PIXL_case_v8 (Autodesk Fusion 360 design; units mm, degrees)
part number: 0.96Oled_W_4_Buttons
base_feature "Base Feature"
work_plane "WorkPlane1" AlongDistance -6.5 ExtraOffset 0
sketch "Sketch1" plane through (0, 0, -6.5) normal (0, 0, 1) x axis (1, 0, 0)
  line L1 (24.2, -27.5) -> (-24.2, -27.5)
  line L2 (24.2, 15.7) -> (24.2, -27.5)
  line L3 (-24.2, 15.7) -> (24.2, 15.7)
  line L4 (-24.2, -27.5) -> (-24.2, 15.7)
extrude "Extrude1" new body sketch "Sketch1" along normal blind 11.8
fillet "Fillet1" radius 5
fillet "Fillet2" radius 1.4
work_plane "WorkPlane2" AlongDistance -6.5 ExtraOffset 0
sketch "Sketch2" plane through (0, 0, -6.5) normal (0, 0, 1) x axis (1, 0, 0)
  line L1 (22.2, -25.5) -> (-22.2, -25.5)
  line L2 (22.2, 13.7) -> (22.2, -25.5)
  line L3 (-22.2, 13.7) -> (22.2, 13.7)
  line L4 (-22.2, -25.5) -> (-22.2, 13.7)
extrude "Extrude2" cut sketch "Sketch2" along normal blind 9.3
fillet "Fillet3" radius 1.7
work_plane "WorkPlane3" AlongDistance 2.79 ExtraOffset 0
sketch "Sketch3" plane through (0, 0, 2.79) normal (0, 0, 1) x axis (1, 0, 0)
  line L1 (20.7, -11.3) -> (11, -11.3)
  line L2 (20.7, 11.7) -> (20.7, -11.3)
  line L3 (11, 11.7) -> (20.7, 11.7)
  line L4 (11, -11.3) -> (11, 11.7)
extrude "Extrude3" cut sketch "Sketch3" along normal blind 1.56
work_plane "WorkPlane4" AlongDistance 2.79 ExtraOffset 0
sketch "Sketch4" plane through (0, 0, 2.79) normal (0, 0, 1) x axis (1, 0, 0)
  line L1 (10, 9.6) -> (-10.8, 9.6)
  line L2 (10, 12.2) -> (10, 9.6)
  line L3 (-10.8, 12.2) -> (10, 12.2)
  line L4 (-10.8, 9.6) -> (-10.8, 12.2)
extrude "Extrude4" cut sketch "Sketch4" along normal blind 0.91
work_plane "WorkPlane5" AlongDistance 4.34 ExtraOffset 0
sketch "Sketch5" plane through (0, 0, 4.34) normal (0, 0, 1) x axis (1, 0, 0)
  line L1 (12.1, 5.6) -> (11.5, 5.6)
  line L2 (12.1, 11.8) -> (12.1, 5.6)
  line L3 (11.5, 11.8) -> (12.1, 11.8)
  line L4 (11.5, 5.6) -> (11.5, 11.8)
extrude "Extrude5" cut sketch "Sketch5" along normal blind 1.06
work_plane "WorkPlane6" AlongDistance 4.34 ExtraOffset 0
sketch "Sketch6" plane through (0, 0, 4.34) normal (0, 0, 1) x axis (1, 0, 0)
  line L1 (19.6, 11.2) -> (11.5, 11.2)
  line L2 (19.6, 11.8) -> (19.6, 11.2)
  line L3 (11.5, 11.8) -> (19.6, 11.8)
  line L4 (11.5, 11.2) -> (11.5, 11.8)
extrude "Extrude6" cut sketch "Sketch6" along normal blind 1.06
work_plane "WorkPlane7" AlongDistance 4.34 ExtraOffset 0
sketch "Sketch7" plane through (0, 0, 4.34) normal (0, 0, 1) x axis (1, 0, 0)
  line L1 (19.6, 5.6) -> (11.5, 5.6)
  line L2 (19.6, 6.2) -> (19.6, 5.6)
  line L3 (11.5, 6.2) -> (19.6, 6.2)
  line L4 (11.5, 5.6) -> (11.5, 6.2)
extrude "Extrude7" cut sketch "Sketch7" along normal blind 1.06
work_plane "WorkPlane8" AlongDistance 4.34 ExtraOffset 0
sketch "Sketch8" plane through (0, 0, 4.34) normal (0, 0, 1) x axis (1, 0, 0)
  line L1 (12.1, -0.07) -> (11.5, -0.07)
  line L2 (12.1, 6.13) -> (12.1, -0.07)
  line L3 (11.5, 6.13) -> (12.1, 6.13)
  line L4 (11.5, -0.07) -> (11.5, 6.13)
extrude "Extrude8" cut sketch "Sketch8" along normal blind 1.06
work_plane "WorkPlane9" AlongDistance 4.34 ExtraOffset 0
sketch "Sketch9" plane through (0, 0, 4.34) normal (0, 0, 1) x axis (1, 0, 0)
  line L1 (19.6, 5.53) -> (11.5, 5.53)
  line L2 (19.6, 6.13) -> (19.6, 5.53)
  line L3 (11.5, 6.13) -> (19.6, 6.13)
  line L4 (11.5, 5.53) -> (11.5, 6.13)
extrude "Extrude9" cut sketch "Sketch9" along normal blind 1.06
work_plane "WorkPlane10" AlongDistance 4.34 ExtraOffset 0
sketch "Sketch10" plane through (0, 0, 4.34) normal (0, 0, 1) x axis (1, 0, 0)
  line L1 (19.6, -0.07) -> (11.5, -0.07)
  line L2 (19.6, 0.53) -> (19.6, -0.07)
  line L3 (11.5, 0.53) -> (19.6, 0.53)
  line L4 (11.5, -0.07) -> (11.5, 0.53)
extrude "Extrude10" cut sketch "Sketch10" along normal blind 1.06
work_plane "WorkPlane11" AlongDistance 4.34 ExtraOffset 0
sketch "Sketch11" plane through (0, 0, 4.34) normal (0, 0, 1) x axis (1, 0, 0)
  line L1 (12.1, -5.73) -> (11.5, -5.73)
  line L2 (12.1, 0.47) -> (12.1, -5.73)
  line L3 (11.5, 0.47) -> (12.1, 0.47)
  line L4 (11.5, -5.73) -> (11.5, 0.47)
extrude "Extrude11" cut sketch "Sketch11" along normal blind 1.06
work_plane "WorkPlane12" AlongDistance 4.34 ExtraOffset 0
sketch "Sketch12" plane through (0, 0, 4.34) normal (0, 0, 1) x axis (1, 0, 0)
  line L1 (19.6, -0.13) -> (11.5, -0.13)
  line L2 (19.6, 0.47) -> (19.6, -0.13)
  line L3 (11.5, 0.47) -> (19.6, 0.47)
  line L4 (11.5, -0.13) -> (11.5, 0.47)
extrude "Extrude12" cut sketch "Sketch12" along normal blind 1.06
work_plane "WorkPlane13" AlongDistance 4.34 ExtraOffset 0
sketch "Sketch13" plane through (0, 0, 4.34) normal (0, 0, 1) x axis (1, 0, 0)
  line L1 (19.6, -5.73) -> (11.5, -5.73)
  line L2 (19.6, -5.13) -> (19.6, -5.73)
  line L3 (11.5, -5.13) -> (19.6, -5.13)
  line L4 (11.5, -5.73) -> (11.5, -5.13)
extrude "Extrude13" cut sketch "Sketch13" along normal blind 1.06
work_plane "WorkPlane14" AlongDistance 4.34 ExtraOffset 0
sketch "Sketch14" plane through (0, 0, 4.34) normal (0, 0, 1) x axis (1, 0, 0)
  line L1 (12.1, -11.4) -> (11.5, -11.4)
  line L2 (12.1, -5.2) -> (12.1, -11.4)
  line L3 (11.5, -5.2) -> (12.1, -5.2)
  line L4 (11.5, -11.4) -> (11.5, -5.2)
extrude "Extrude14" cut sketch "Sketch14" along normal blind 1.06
work_plane "WorkPlane15" AlongDistance 4.34 ExtraOffset 0
sketch "Sketch15" plane through (0, 0, 4.34) normal (0, 0, 1) x axis (1, 0, 0)
  line L1 (19.6, -5.8) -> (11.5, -5.8)
  line L2 (19.6, -5.2) -> (19.6, -5.8)
  line L3 (11.5, -5.2) -> (19.6, -5.2)
  line L4 (11.5, -5.8) -> (11.5, -5.2)
extrude "Extrude15" cut sketch "Sketch15" along normal blind 1.06
work_plane "WorkPlane16" AlongDistance 4.34 ExtraOffset 0
sketch "Sketch16" plane through (0, 0, 4.34) normal (0, 0, 1) x axis (1, 0, 0)
  line L1 (19.6, -11.4) -> (11.5, -11.4)
  line L2 (19.6, -10.8) -> (19.6, -11.4)
  line L3 (11.5, -10.8) -> (19.6, -10.8)
  line L4 (11.5, -11.4) -> (11.5, -10.8)
extrude "Extrude16" cut sketch "Sketch16" along normal blind 1.06
work_plane "WorkPlane17" AlongDistance 4.34 ExtraOffset 0
sketch "Sketch17" plane through (0, 0, 4.34) normal (0, 0, 1) x axis (1, 0, 0)
  line L1 (20.7, 6.2) -> (18.4, 6.2)
  line L2 (20.7, 11.2) -> (20.7, 6.2)
  line L3 (18.4, 11.2) -> (20.7, 11.2)
  line L4 (18.4, 6.2) -> (18.4, 11.2)
extrude "Extrude17" cut sketch "Sketch17" along normal blind 0.46
work_plane "WorkPlane18" AlongDistance 4.34 ExtraOffset 0
sketch "Sketch18" plane through (0, 0, 4.34) normal (0, 0, 1) x axis (1, 0, 0)
  line L1 (20.7, 0.53) -> (18.4, 0.53)
  line L2 (20.7, 5.53) -> (20.7, 0.53)
  line L3 (18.4, 5.53) -> (20.7, 5.53)
  line L4 (18.4, 0.53) -> (18.4, 5.53)
extrude "Extrude18" cut sketch "Sketch18" along normal blind 0.46
work_plane "WorkPlane19" AlongDistance 4.34 ExtraOffset 0
sketch "Sketch19" plane through (0, 0, 4.34) normal (0, 0, 1) x axis (1, 0, 0)
  line L1 (20.7, -5.13) -> (18.4, -5.13)
  line L2 (20.7, -0.13) -> (20.7, -5.13)
  line L3 (18.4, -0.13) -> (20.7, -0.13)
  line L4 (18.4, -5.13) -> (18.4, -0.13)
extrude "Extrude19" cut sketch "Sketch19" along normal blind 0.46
work_plane "WorkPlane20" AlongDistance 4.34 ExtraOffset 0
sketch "Sketch20" plane through (0, 0, 4.34) normal (0, 0, 1) x axis (1, 0, 0)
  line L1 (20.7, -10.8) -> (18.4, -10.8)
  line L2 (20.7, -5.8) -> (20.7, -10.8)
  line L3 (18.4, -5.8) -> (20.7, -5.8)
  line L4 (18.4, -10.8) -> (18.4, -5.8)
extrude "Extrude20" cut sketch "Sketch20" along normal blind 0.46
work_plane "WorkPlane21" AlongDistance 2.79 ExtraOffset 0
sketch "Sketch21" plane through (0, 0, 2.79) normal (0, 0, 1) x axis (1, 0, 0)
  line L1 (7, -6.6) -> (-16.3, -6.6)
  line L2 (7, 6.4) -> (7, -6.6)
  line L3 (-16.3, 6.4) -> (7, 6.4)
  line L4 (-16.3, -6.6) -> (-16.3, 6.4)
extrude "Extrude21" cut sketch "Sketch21" along normal blind 2.61
chamfer "Chamfer1" distance 1.2
work_plane "WorkPlane22" AlongDistance 1.6 ExtraOffset 0
sketch "Sketch22" plane through (0, 0, 1.6) normal (0, 0, 1) x axis (1, 0, 0)
  circle C1 centre (-20.5, -12) radius 1.5
extrude "Extrude22" add sketch "Sketch22" along normal blind 1.21
work_plane "WorkPlane23" AlongDistance 0.3 ExtraOffset 0
sketch "Sketch23" plane through (0, 0, 0.3) normal (0, 0, 1) x axis (1, 0, 0)
  circle C1 centre (-20.5, -12) radius 0.88
extrude "Extrude23" add sketch "Sketch23" along normal blind 1.31
work_plane "WorkPlane24" AlongDistance 1.6 ExtraOffset 0
sketch "Sketch24" plane through (0, 0, 1.6) normal (0, 0, 1) x axis (1, 0, 0)
  circle C1 centre (-20.5, 12) radius 1.5
extrude "Extrude24" add sketch "Sketch24" along normal blind 1.21
work_plane "WorkPlane25" AlongDistance 0.3 ExtraOffset 0
sketch "Sketch25" plane through (0, 0, 0.3) normal (0, 0, 1) x axis (1, 0, 0)
  circle C1 centre (-20.5, 12) radius 0.88
extrude "Extrude25" add sketch "Sketch25" along normal blind 1.31
work_plane "WorkPlane26" AlongDistance 1.6 ExtraOffset 0
sketch "Sketch26" plane through (0, 0, 1.6) normal (0, 0, 1) x axis (1, 0, 0)
  circle C1 centre (20.5, -12) radius 1.5
extrude "Extrude26" add sketch "Sketch26" along normal blind 1.21
work_plane "WorkPlane27" AlongDistance 0.3 ExtraOffset 0
sketch "Sketch27" plane through (0, 0, 0.3) normal (0, 0, 1) x axis (1, 0, 0)
  circle C1 centre (20.5, -12) radius 0.88
extrude "Extrude27" add sketch "Sketch27" along normal blind 1.31
work_plane "WorkPlane28" AlongDistance 1.6 ExtraOffset 0
sketch "Sketch28" plane through (0, 0, 1.6) normal (0, 0, 1) x axis (1, 0, 0)
  circle C1 centre (20.5, 12) radius 1.5
extrude "Extrude28" add sketch "Sketch28" along normal blind 1.21
work_plane "WorkPlane29" AlongDistance 0.3 ExtraOffset 0
sketch "Sketch29" plane through (0, 0, 0.3) normal (0, 0, 1) x axis (1, 0, 0)
  circle C1 centre (20.5, 12) radius 0.88
extrude "Extrude29" add sketch "Sketch29" along normal blind 1.31
work_plane "WorkPlane30" AlongDistance 5.3 ExtraOffset 0
sketch "Sketch30" plane through (0, 0, 5.3) normal (0, 0, 1) x axis (1, 0, 0)
  line L1 (-16.5, -17.8) -> (-19.8, -17.8)
  line L2 (-16.5, -16.7) -> (-16.5, -17.8)
  line L3 (-19.8, -16.7) -> (-16.5, -16.7)
  line L4 (-19.8, -17.8) -> (-19.8, -16.7)
  line L5 (-18.7, -18.9) -> (-19.8, -18.9)
  line L6 (-18.7, -17.8) -> (-18.7, -18.9)
  line L7 (-19.8, -17.8) -> (-18.7, -17.8)
  line L8 (-19.8, -18.9) -> (-19.8, -17.8)
  line L9 (-15.4, -18.9) -> (-16.5, -18.9)
  line L10 (-15.4, -17.8) -> (-15.4, -18.9)
  line L11 (-16.5, -17.8) -> (-15.4, -17.8)
  line L12 (-16.5, -18.9) -> (-16.5, -17.8)
  line L13 (-18.7, -20) -> (-19.8, -20)
  line L14 (-18.7, -18.9) -> (-18.7, -20)
  line L15 (-19.8, -18.9) -> (-18.7, -18.9)
  line L16 (-19.8, -20) -> (-19.8, -18.9)
  line L17 (-15.4, -20) -> (-16.5, -20)
  line L18 (-15.4, -18.9) -> (-15.4, -20)
  line L19 (-16.5, -18.9) -> (-15.4, -18.9)
  line L20 (-16.5, -20) -> (-16.5, -18.9)
  line L21 (-16.5, -21.1) -> (-19.8, -21.1)
  line L22 (-16.5, -20) -> (-16.5, -21.1)
  line L23 (-19.8, -20) -> (-16.5, -20)
  line L24 (-19.8, -21.1) -> (-19.8, -20)
  line L25 (-18.7, -22.2) -> (-19.8, -22.2)
  line L26 (-18.7, -21.1) -> (-18.7, -22.2)
  line L27 (-19.8, -21.1) -> (-18.7, -21.1)
  line L28 (-19.8, -22.2) -> (-19.8, -21.1)
  line L29 (-18.7, -23.3) -> (-19.8, -23.3)
  line L30 (-18.7, -22.2) -> (-18.7, -23.3)
  line L31 (-19.8, -22.2) -> (-18.7, -22.2)
  line L32 (-19.8, -23.3) -> (-19.8, -22.2)
  line L33 (-13.2, -17.8) -> (-14.3, -17.8)
  line L34 (-13.2, -16.7) -> (-13.2, -17.8)
  line L35 (-14.3, -16.7) -> (-13.2, -16.7)
  line L36 (-14.3, -17.8) -> (-14.3, -16.7)
  line L37 (-13.2, -20) -> (-14.3, -20)
  line L38 (-13.2, -18.9) -> (-13.2, -20)
  line L39 (-14.3, -18.9) -> (-13.2, -18.9)
  line L40 (-14.3, -20) -> (-14.3, -18.9)
  line L41 (-13.2, -21.1) -> (-14.3, -21.1)
  line L42 (-13.2, -20) -> (-13.2, -21.1)
  line L43 (-14.3, -20) -> (-13.2, -20)
  line L44 (-14.3, -21.1) -> (-14.3, -20)
  line L45 (-13.2, -22.2) -> (-14.3, -22.2)
  line L46 (-13.2, -21.1) -> (-13.2, -22.2)
  line L47 (-14.3, -21.1) -> (-13.2, -21.1)
  line L48 (-14.3, -22.2) -> (-14.3, -21.1)
  line L49 (-13.2, -23.3) -> (-14.3, -23.3)
  line L50 (-13.2, -22.2) -> (-13.2, -23.3)
  line L51 (-14.3, -22.2) -> (-13.2, -22.2)
  line L52 (-14.3, -23.3) -> (-14.3, -22.2)
  line L53 (-11, -17.8) -> (-12.1, -17.8)
  line L54 (-11, -16.7) -> (-11, -17.8)
  line L55 (-12.1, -16.7) -> (-11, -16.7)
  line L56 (-12.1, -17.8) -> (-12.1, -16.7)
  line L57 (-7.7, -17.8) -> (-8.8, -17.8)
  line L58 (-7.7, -16.7) -> (-7.7, -17.8)
  line L59 (-8.8, -16.7) -> (-7.7, -16.7)
  line L60 (-8.8, -17.8) -> (-8.8, -16.7)
  line L61 (-11, -18.9) -> (-12.1, -18.9)
  line L62 (-11, -17.8) -> (-11, -18.9)
  line L63 (-12.1, -17.8) -> (-11, -17.8)
  line L64 (-12.1, -18.9) -> (-12.1, -17.8)
  line L65 (-7.7, -18.9) -> (-8.8, -18.9)
  line L66 (-7.7, -17.8) -> (-7.7, -18.9)
  line L67 (-8.8, -17.8) -> (-7.7, -17.8)
  line L68 (-8.8, -18.9) -> (-8.8, -17.8)
  line L69 (-8.8, -20) -> (-11, -20)
  line L70 (-8.8, -18.9) -> (-8.8, -20)
  line L71 (-11, -18.9) -> (-8.8, -18.9)
  line L72 (-11, -20) -> (-11, -18.9)
  line L73 (-8.8, -21.1) -> (-11, -21.1)
  line L74 (-8.8, -20) -> (-8.8, -21.1)
  line L75 (-11, -20) -> (-8.8, -20)
  line L76 (-11, -21.1) -> (-11, -20)
  line L77 (-11, -22.2) -> (-12.1, -22.2)
  line L78 (-11, -21.1) -> (-11, -22.2)
  line L79 (-12.1, -21.1) -> (-11, -21.1)
  line L80 (-12.1, -22.2) -> (-12.1, -21.1)
  line L81 (-7.7, -22.2) -> (-8.8, -22.2)
  line L82 (-7.7, -21.1) -> (-7.7, -22.2)
  line L83 (-8.8, -21.1) -> (-7.7, -21.1)
  line L84 (-8.8, -22.2) -> (-8.8, -21.1)
  line L85 (-11, -23.3) -> (-12.1, -23.3)
  line L86 (-11, -22.2) -> (-11, -23.3)
  line L87 (-12.1, -22.2) -> (-11, -22.2)
  line L88 (-12.1, -23.3) -> (-12.1, -22.2)
  line L89 (-7.7, -23.3) -> (-8.8, -23.3)
  line L90 (-7.7, -22.2) -> (-7.7, -23.3)
  line L91 (-8.8, -22.2) -> (-7.7, -22.2)
  line L92 (-8.8, -23.3) -> (-8.8, -22.2)
  line L93 (-5.5, -17.8) -> (-6.6, -17.8)
  line L94 (-5.5, -16.7) -> (-5.5, -17.8)
  line L95 (-6.6, -16.7) -> (-5.5, -16.7)
  line L96 (-6.6, -17.8) -> (-6.6, -16.7)
  line L97 (-5.5, -18.9) -> (-6.6, -18.9)
  line L98 (-5.5, -17.8) -> (-5.5, -18.9)
  line L99 (-6.6, -17.8) -> (-5.5, -17.8)
  line L100 (-6.6, -18.9) -> (-6.6, -17.8)
  line L101 (-5.5, -20) -> (-6.6, -20)
  line L102 (-5.5, -18.9) -> (-5.5, -20)
  line L103 (-6.6, -18.9) -> (-5.5, -18.9)
  line L104 (-6.6, -20) -> (-6.6, -18.9)
  line L105 (-5.5, -21.1) -> (-6.6, -21.1)
  line L106 (-5.5, -20) -> (-5.5, -21.1)
  line L107 (-6.6, -20) -> (-5.5, -20)
  line L108 (-6.6, -21.1) -> (-6.6, -20)
  line L109 (-5.5, -22.2) -> (-6.6, -22.2)
  line L110 (-5.5, -21.1) -> (-5.5, -22.2)
  line L111 (-6.6, -21.1) -> (-5.5, -21.1)
  line L112 (-6.6, -22.2) -> (-6.6, -21.1)
  line L113 (-2.2, -23.3) -> (-6.6, -23.3)
  line L114 (-2.2, -22.2) -> (-2.2, -23.3)
  line L115 (-6.6, -22.2) -> (-2.2, -22.2)
  line L116 (-6.6, -23.3) -> (-6.6, -22.2)
extrude "Extrude30" cut sketch "Sketch30" against normal blind 0.4
work_plane "WorkPlane31" AlongDistance 5.3 ExtraOffset 0
sketch "Sketch31" plane through (0, 0, 5.3) normal (0, 0, 1) x axis (1, 0, 0)
  line L1 (3.25, -22.25) -> (2.5, -22.25)
  line L2 (3.25, -21.5) -> (3.25, -22.25)
  line L3 (2.5, -21.5) -> (3.25, -21.5)
  line L4 (2.5, -22.25) -> (2.5, -21.5)
  line L5 (4.5, -22.25) -> (3.75, -22.25)
  line L6 (4.5, -21.5) -> (4.5, -22.25)
  line L7 (3.75, -21.5) -> (4.5, -21.5)
  line L8 (3.75, -22.25) -> (3.75, -21.5)
  line L9 (5.75, -22.25) -> (5, -22.25)
  line L10 (5.75, -21.5) -> (5.75, -22.25)
  line L11 (5, -21.5) -> (5.75, -21.5)
  line L12 (5, -22.25) -> (5, -21.5)
  line L13 (7, -22.25) -> (6.25, -22.25)
  line L14 (7, -21.5) -> (7, -22.25)
  line L15 (6.25, -21.5) -> (7, -21.5)
  line L16 (6.25, -22.25) -> (6.25, -21.5)
  line L17 (8.25, -22.25) -> (7.5, -22.25)
  line L18 (8.25, -21.5) -> (8.25, -22.25)
  line L19 (7.5, -21.5) -> (8.25, -21.5)
  line L20 (7.5, -22.25) -> (7.5, -21.5)
  line L21 (9.5, -22.25) -> (8.75, -22.25)
  line L22 (9.5, -21.5) -> (9.5, -22.25)
  line L23 (8.75, -21.5) -> (9.5, -21.5)
  line L24 (8.75, -22.25) -> (8.75, -21.5)
  line L25 (10.75, -22.25) -> (10, -22.25)
  line L26 (10.75, -21.5) -> (10.75, -22.25)
  line L27 (10, -21.5) -> (10.75, -21.5)
  line L28 (10, -22.25) -> (10, -21.5)
  line L29 (13.25, -22.25) -> (12.5, -22.25)
  line L30 (13.25, -21.5) -> (13.25, -22.25)
  line L31 (12.5, -21.5) -> (13.25, -21.5)
  line L32 (12.5, -22.25) -> (12.5, -21.5)
  line L33 (15.75, -22.25) -> (15, -22.25)
  line L34 (15.75, -21.5) -> (15.75, -22.25)
  line L35 (15, -21.5) -> (15.75, -21.5)
  line L36 (15, -22.25) -> (15, -21.5)
  line L37 (3.25, -21) -> (2.5, -21)
  line L38 (3.25, -20.25) -> (3.25, -21)
  line L39 (2.5, -20.25) -> (3.25, -20.25)
  line L40 (2.5, -21) -> (2.5, -20.25)
  line L41 (4.5, -21) -> (3.75, -21)
  line L42 (4.5, -20.25) -> (4.5, -21)
  line L43 (3.75, -20.25) -> (4.5, -20.25)
  line L44 (3.75, -21) -> (3.75, -20.25)
  line L45 (7, -21) -> (6.25, -21)
  line L46 (7, -20.25) -> (7, -21)
  line L47 (6.25, -20.25) -> (7, -20.25)
  line L48 (6.25, -21) -> (6.25, -20.25)
  line L49 (9.5, -21) -> (8.75, -21)
  line L50 (9.5, -20.25) -> (9.5, -21)
  line L51 (8.75, -20.25) -> (9.5, -20.25)
  line L52 (8.75, -21) -> (8.75, -20.25)
  line L53 (12, -21) -> (11.25, -21)
  line L54 (12, -20.25) -> (12, -21)
  line L55 (11.25, -20.25) -> (12, -20.25)
  line L56 (11.25, -21) -> (11.25, -20.25)
  line L57 (3.25, -19.75) -> (2.5, -19.75)
  line L58 (3.25, -19) -> (3.25, -19.75)
  line L59 (2.5, -19) -> (3.25, -19)
  line L60 (2.5, -19.75) -> (2.5, -19)
  line L61 (4.5, -19.75) -> (3.75, -19.75)
  line L62 (4.5, -19) -> (4.5, -19.75)
  line L63 (3.75, -19) -> (4.5, -19)
  line L64 (3.75, -19.75) -> (3.75, -19)
  line L65 (5.75, -19.75) -> (5, -19.75)
  line L66 (5.75, -19) -> (5.75, -19.75)
  line L67 (5, -19) -> (5.75, -19)
  line L68 (5, -19.75) -> (5, -19)
  line L69 (7, -19.75) -> (6.25, -19.75)
  line L70 (7, -19) -> (7, -19.75)
  line L71 (6.25, -19) -> (7, -19)
  line L72 (6.25, -19.75) -> (6.25, -19)
  line L73 (8.25, -19.75) -> (7.5, -19.75)
  line L74 (8.25, -19) -> (8.25, -19.75)
  line L75 (7.5, -19) -> (8.25, -19)
  line L76 (7.5, -19.75) -> (7.5, -19)
  line L77 (10.75, -19.75) -> (10, -19.75)
  line L78 (10.75, -19) -> (10.75, -19.75)
  line L79 (10, -19) -> (10.75, -19)
  line L80 (10, -19.75) -> (10, -19)
  line L81 (13.25, -19.75) -> (12.5, -19.75)
  line L82 (13.25, -19) -> (13.25, -19.75)
  line L83 (12.5, -19) -> (13.25, -19)
  line L84 (12.5, -19.75) -> (12.5, -19)
  line L85 (15.75, -19.75) -> (15, -19.75)
  line L86 (15.75, -19) -> (15.75, -19.75)
  line L87 (15, -19) -> (15.75, -19)
  line L88 (15, -19.75) -> (15, -19)
  line L89 (3.25, -18.5) -> (2.5, -18.5)
  line L90 (3.25, -17.75) -> (3.25, -18.5)
  line L91 (2.5, -17.75) -> (3.25, -17.75)
  line L92 (2.5, -18.5) -> (2.5, -17.75)
  line L93 (4.5, -18.5) -> (3.75, -18.5)
  line L94 (4.5, -17.75) -> (4.5, -18.5)
  line L95 (3.75, -17.75) -> (4.5, -17.75)
  line L96 (3.75, -18.5) -> (3.75, -17.75)
  line L97 (7, -18.5) -> (6.25, -18.5)
  line L98 (7, -17.75) -> (7, -18.5)
  line L99 (6.25, -17.75) -> (7, -17.75)
  line L100 (6.25, -18.5) -> (6.25, -17.75)
  line L101 (9.5, -18.5) -> (8.75, -18.5)
  line L102 (9.5, -17.75) -> (9.5, -18.5)
  line L103 (8.75, -17.75) -> (9.5, -17.75)
  line L104 (8.75, -18.5) -> (8.75, -17.75)
  line L105 (12, -18.5) -> (11.25, -18.5)
  line L106 (12, -17.75) -> (12, -18.5)
  line L107 (11.25, -17.75) -> (12, -17.75)
  line L108 (11.25, -18.5) -> (11.25, -17.75)
extrude "Extrude31" cut sketch "Sketch31" against normal blind 0.35
work_plane "WorkPlane32" AlongDistance 5.3 ExtraOffset 0
sketch "Sketch32" plane through (0, 0, 5.3) normal (0, 0, 1) x axis (1, 0, 0)
  line L1 (17.125, 9.375) -> (16.675, 9.375)
  line L2 (17.125, 9.825) -> (17.125, 9.375)
  line L3 (16.675, 9.825) -> (17.125, 9.825)
  line L4 (16.675, 9.375) -> (16.675, 9.825)
  line L5 (17.575, 8.925) -> (16.225, 8.925)
  line L6 (17.575, 9.375) -> (17.575, 8.925)
  line L7 (16.225, 9.375) -> (17.575, 9.375)
  line L8 (16.225, 8.925) -> (16.225, 9.375)
  line L9 (16.675, 8.475) -> (15.775, 8.475)
  line L10 (16.675, 8.925) -> (16.675, 8.475)
  line L11 (15.775, 8.925) -> (16.675, 8.925)
  line L12 (15.775, 8.475) -> (15.775, 8.925)
  line L13 (18.025, 8.475) -> (17.125, 8.475)
  line L14 (18.025, 8.925) -> (18.025, 8.475)
  line L15 (17.125, 8.925) -> (18.025, 8.925)
  line L16 (17.125, 8.475) -> (17.125, 8.925)
  line L17 (16.225, 8.025) -> (15.325, 8.025)
  line L18 (16.225, 8.475) -> (16.225, 8.025)
  line L19 (15.325, 8.475) -> (16.225, 8.475)
  line L20 (15.325, 8.025) -> (15.325, 8.475)
  line L21 (18.475, 8.025) -> (17.575, 8.025)
  line L22 (18.475, 8.475) -> (18.475, 8.025)
  line L23 (17.575, 8.475) -> (18.475, 8.475)
  line L24 (17.575, 8.025) -> (17.575, 8.475)
  line L25 (15.775, 7.575) -> (15.325, 7.575)
  line L26 (15.775, 8.025) -> (15.775, 7.575)
  line L27 (15.325, 8.025) -> (15.775, 8.025)
  line L28 (15.325, 7.575) -> (15.325, 8.025)
  line L29 (18.475, 7.575) -> (18.025, 7.575)
  line L30 (18.475, 8.025) -> (18.475, 7.575)
  line L31 (18.025, 8.025) -> (18.475, 8.025)
  line L32 (18.025, 7.575) -> (18.025, 8.025)
  line L33 (15.775, 3.705) -> (15.325, 3.705)
  line L34 (15.775, 4.155) -> (15.775, 3.705)
  line L35 (15.325, 4.155) -> (15.775, 4.155)
  line L36 (15.325, 3.705) -> (15.325, 4.155)
  line L37 (18.475, 3.705) -> (18.025, 3.705)
  line L38 (18.475, 4.155) -> (18.475, 3.705)
  line L39 (18.025, 4.155) -> (18.475, 4.155)
  line L40 (18.025, 3.705) -> (18.025, 4.155)
  line L41 (16.225, 3.255) -> (15.325, 3.255)
  line L42 (16.225, 3.705) -> (16.225, 3.255)
  line L43 (15.325, 3.705) -> (16.225, 3.705)
  line L44 (15.325, 3.255) -> (15.325, 3.705)
  line L45 (18.475, 3.255) -> (17.575, 3.255)
  line L46 (18.475, 3.705) -> (18.475, 3.255)
  line L47 (17.575, 3.705) -> (18.475, 3.705)
  line L48 (17.575, 3.255) -> (17.575, 3.705)
  line L49 (16.675, 2.805) -> (15.775, 2.805)
  line L50 (16.675, 3.255) -> (16.675, 2.805)
  line L51 (15.775, 3.255) -> (16.675, 3.255)
  line L52 (15.775, 2.805) -> (15.775, 3.255)
  line L53 (18.025, 2.805) -> (17.125, 2.805)
  line L54 (18.025, 3.255) -> (18.025, 2.805)
  line L55 (17.125, 3.255) -> (18.025, 3.255)
  line L56 (17.125, 2.805) -> (17.125, 3.255)
  line L57 (17.575, 2.355) -> (16.225, 2.355)
  line L58 (17.575, 2.805) -> (17.575, 2.355)
  line L59 (16.225, 2.805) -> (17.575, 2.805)
  line L60 (16.225, 2.355) -> (16.225, 2.805)
  line L61 (17.125, 1.905) -> (16.675, 1.905)
  line L62 (17.125, 2.355) -> (17.125, 1.905)
  line L63 (16.675, 2.355) -> (17.125, 2.355)
  line L64 (16.675, 1.905) -> (16.675, 2.355)
  line L65 (18.475, -1.955) -> (15.325, -1.955)
  line L66 (18.475, -1.505) -> (18.475, -1.955)
  line L67 (15.325, -1.505) -> (18.475, -1.505)
  line L68 (15.325, -1.955) -> (15.325, -1.505)
  line L69 (18.475, -2.855) -> (15.325, -2.855)
  line L70 (18.475, -2.405) -> (18.475, -2.855)
  line L71 (15.325, -2.405) -> (18.475, -2.405)
  line L72 (15.325, -2.855) -> (15.325, -2.405)
  line L73 (18.475, -3.755) -> (15.325, -3.755)
  line L74 (18.475, -3.305) -> (18.475, -3.755)
  line L75 (15.325, -3.305) -> (18.475, -3.305)
  line L76 (15.325, -3.755) -> (15.325, -3.305)
  line L77 (16.675, -7.175) -> (16.225, -7.175)
  line L78 (16.675, -6.725) -> (16.675, -7.175)
  line L79 (16.225, -6.725) -> (16.675, -6.725)
  line L80 (16.225, -7.175) -> (16.225, -6.725)
  line L81 (16.675, -7.625) -> (15.775, -7.625)
  line L82 (16.675, -7.175) -> (16.675, -7.625)
  line L83 (15.775, -7.175) -> (16.675, -7.175)
  line L84 (15.775, -7.625) -> (15.775, -7.175)
  line L85 (18.025, -8.075) -> (15.325, -8.075)
  line L86 (18.025, -7.625) -> (18.025, -8.075)
  line L87 (15.325, -7.625) -> (18.025, -7.625)
  line L88 (15.325, -8.075) -> (15.325, -7.625)
  line L89 (16.675, -8.525) -> (15.775, -8.525)
  line L90 (16.675, -8.075) -> (16.675, -8.525)
  line L91 (15.775, -8.075) -> (16.675, -8.075)
  line L92 (15.775, -8.525) -> (15.775, -8.075)
  line L93 (18.475, -8.525) -> (18.025, -8.525)
  line L94 (18.475, -8.075) -> (18.475, -8.525)
  line L95 (18.025, -8.075) -> (18.475, -8.075)
  line L96 (18.025, -8.525) -> (18.025, -8.075)
  line L97 (16.675, -8.975) -> (16.225, -8.975)
  line L98 (16.675, -8.525) -> (16.675, -8.975)
  line L99 (16.225, -8.525) -> (16.675, -8.525)
  line L100 (16.225, -8.975) -> (16.225, -8.525)
  line L101 (18.475, -8.975) -> (18.025, -8.975)
  line L102 (18.475, -8.525) -> (18.475, -8.975)
  line L103 (18.025, -8.525) -> (18.475, -8.525)
  line L104 (18.025, -8.975) -> (18.025, -8.525)
  line L105 (18.475, -9.425) -> (18.025, -9.425)
  line L106 (18.475, -8.975) -> (18.475, -9.425)
  line L107 (18.025, -8.975) -> (18.475, -8.975)
  line L108 (18.025, -9.425) -> (18.025, -8.975)
  line L109 (18.025, -9.875) -> (15.775, -9.875)
  line L110 (18.025, -9.425) -> (18.025, -9.875)
  line L111 (15.775, -9.425) -> (18.025, -9.425)
  line L112 (15.775, -9.875) -> (15.775, -9.425)
extrude "Extrude32" cut sketch "Sketch32" against normal blind 0.3
work_plane "WorkPlane33" AlongDistance -4.9 ExtraOffset 0
sketch "Sketch33" plane through (0, 0, -4.9) normal (0, 0, 1) x axis (1, 0, 0)
  line L1 (24.7, -21) -> (21.7, -21)
  line L2 (24.7, -11) -> (24.7, -21)
  line L3 (21.7, -11) -> (24.7, -11)
  line L4 (21.7, -21) -> (21.7, -11)
extrude "Extrude33" cut sketch "Sketch33" along normal blind 4
work_plane "WorkPlane34" AlongDistance -5.9 ExtraOffset 0
sketch "Sketch34" plane through (0, 0, -5.9) normal (0, 0, 1) x axis (1, 0, 0)
  line L1 (24.7, -22.5) -> (23.2, -22.5)
  line L2 (24.7, -9.5) -> (24.7, -22.5)
  line L3 (23.2, -9.5) -> (24.7, -9.5)
  line L4 (23.2, -22.5) -> (23.2, -9.5)
extrude "Extrude34" cut sketch "Sketch34" along normal blind 6
work_plane "WorkPlane35" AlongDistance -6.5 ExtraOffset 0
sketch "Sketch35" plane through (0, 0, -6.5) normal (0, 0, 1) x axis (1, 0, 0)
  circle C1 centre (-20.1, -23.4) radius 2
extrude "Extrude35" add sketch "Sketch35" along normal blind 9.31
work_plane "WorkPlane36" AlongDistance -6.5 ExtraOffset 0
sketch "Sketch36" plane through (0, 0, -6.5) normal (0, 0, 1) x axis (1, 0, 0)
  line L1 (-20.1, -25.4) -> (-22.5, -25.4)
  line L2 (-20.1, -21.4) -> (-20.1, -25.4)
  line L3 (-22.5, -21.4) -> (-20.1, -21.4)
  line L4 (-22.5, -25.4) -> (-22.5, -21.4)
extrude "Extrude36" add sketch "Sketch36" along normal blind 9.31
work_plane "WorkPlane37" AlongDistance -6.5 ExtraOffset 0
sketch "Sketch37" plane through (0, 0, -6.5) normal (0, 0, 1) x axis (1, 0, 0)
  line L1 (-18.1, -25.8) -> (-22.1, -25.8)
  line L2 (-18.1, -23.4) -> (-18.1, -25.8)
  line L3 (-22.1, -23.4) -> (-18.1, -23.4)
  line L4 (-22.1, -25.8) -> (-22.1, -23.4)
extrude "Extrude37" add sketch "Sketch37" along normal blind 9.31
work_plane "WorkPlane38" AlongDistance -6.51 ExtraOffset 0
sketch "Sketch38" plane through (0, 0, -6.51) normal (0, 0, 1) x axis (1, 0, 0)
  circle C1 centre (-20.1, -23.4) radius 0.85
extrude "Extrude38" cut sketch "Sketch38" along normal blind 5.51
work_plane "WorkPlane39" AlongDistance -6.5 ExtraOffset 0
sketch "Sketch39" plane through (0, 0, -6.5) normal (0, 0, 1) x axis (1, 0, 0)
  circle C1 centre (-1.7, -23.5) radius 1.9
extrude "Extrude39" add sketch "Sketch39" along normal blind 9.31
work_plane "WorkPlane40" AlongDistance -6.5 ExtraOffset 0
sketch "Sketch40" plane through (0, 0, -6.5) normal (0, 0, 1) x axis (1, 0, 0)
  line L1 (0.2, -25.8) -> (-3.6, -25.8)
  line L2 (0.2, -23.5) -> (0.2, -25.8)
  line L3 (-3.6, -23.5) -> (0.2, -23.5)
  line L4 (-3.6, -25.8) -> (-3.6, -23.5)
extrude "Extrude40" add sketch "Sketch40" along normal blind 9.31
work_plane "WorkPlane41" AlongDistance -6.51 ExtraOffset 0
sketch "Sketch41" plane through (0, 0, -6.51) normal (0, 0, 1) x axis (1, 0, 0)
  circle C1 centre (-1.7, -23.5) radius 0.85
extrude "Extrude41" cut sketch "Sketch41" along normal blind 5.51
work_plane "WorkPlane42" AlongDistance -6 ExtraOffset 0
sketch "Sketch42" plane through (0, 0, -6) normal (0, 0, 1) x axis (1, 0, 0)
  line L1 (19.4, 13.6) -> (10.6, 13.6)
  line L2 (19.4, 14.6) -> (19.4, 13.6)
  line L3 (10.6, 14.6) -> (19.4, 14.6)
  line L4 (10.6, 13.6) -> (10.6, 14.6)
extrude "Extrude42" cut sketch "Sketch42" along normal blind 1.2
work_plane "WorkPlane43" AlongDistance -6.5 ExtraOffset 0
sketch "Sketch43" plane through (0, 0, -6.5) normal (0, 0, 1) x axis (1, 0, 0)
  line L1 (-10.2, -32.1) -> (-12.6, -32.1)
  line L2 (-10.2, -26.5) -> (-10.2, -32.1)
  line L3 (-12.6, -26.5) -> (-10.2, -26.5)
  line L4 (-12.6, -32.1) -> (-12.6, -26.5)
extrude "Extrude43" add sketch "Sketch43" along normal blind 3
work_plane "WorkPlane44" AlongDistance -7.7 ExtraOffset 0
sketch "Sketch44" plane through (0, 0, -7.7) normal (0, 0, 1) x axis (1, 0, 0)
  line L1 (-10.2, -32.1) -> (-12.6, -32.1)
  line L2 (-10.2, -27.7) -> (-10.2, -32.1)
  line L3 (-12.6, -27.7) -> (-10.2, -27.7)
  line L4 (-12.6, -32.1) -> (-12.6, -27.7)
extrude "Extrude44" add sketch "Sketch44" along normal blind 1.21
work_plane "WorkPlane45" AlongDistance -6.5 ExtraOffset 0
sketch "Sketch45" plane through (0, 0, -6.5) normal (0, 0, 1) x axis (1, 0, 0)
  line L1 (-10.2, 14.7) -> (-12.6, 14.7)
  line L2 (-10.2, 20.3) -> (-10.2, 14.7)
  line L3 (-12.6, 20.3) -> (-10.2, 20.3)
  line L4 (-12.6, 14.7) -> (-12.6, 20.3)
extrude "Extrude45" add sketch "Sketch45" along normal blind 3
work_plane "WorkPlane46" AlongDistance -7.7 ExtraOffset 0
sketch "Sketch46" plane through (0, 0, -7.7) normal (0, 0, 1) x axis (1, 0, 0)
  line L1 (-10.2, 15.9) -> (-12.6, 15.9)
  line L2 (-10.2, 20.3) -> (-10.2, 15.9)
  line L3 (-12.6, 20.3) -> (-10.2, 20.3)
  line L4 (-12.6, 15.9) -> (-12.6, 20.3)
extrude "Extrude46" add sketch "Sketch46" along normal blind 1.21
work_plane "WorkPlane47" AlongDistance -6.5 ExtraOffset 0
sketch "Sketch47" plane through (0, 0, -6.5) normal (0, 0, 1) x axis (1, 0, 0)
  line L1 (12.6, -32.1) -> (10.2, -32.1)
  line L2 (12.6, -26.5) -> (12.6, -32.1)
  line L3 (10.2, -26.5) -> (12.6, -26.5)
  line L4 (10.2, -32.1) -> (10.2, -26.5)
extrude "Extrude47" add sketch "Sketch47" along normal blind 3
work_plane "WorkPlane48" AlongDistance -7.7 ExtraOffset 0
sketch "Sketch48" plane through (0, 0, -7.7) normal (0, 0, 1) x axis (1, 0, 0)
  line L1 (12.6, -32.1) -> (10.2, -32.1)
  line L2 (12.6, -27.7) -> (12.6, -32.1)
  line L3 (10.2, -27.7) -> (12.6, -27.7)
  line L4 (10.2, -32.1) -> (10.2, -27.7)
extrude "Extrude48" add sketch "Sketch48" along normal blind 1.21
work_plane "WorkPlane49" AlongDistance -6.5 ExtraOffset 0
sketch "Sketch49" plane through (0, 0, -6.5) normal (0, 0, 1) x axis (1, 0, 0)
  line L1 (12.6, 14.7) -> (10.2, 14.7)
  line L2 (12.6, 20.3) -> (12.6, 14.7)
  line L3 (10.2, 20.3) -> (12.6, 20.3)
  line L4 (10.2, 14.7) -> (10.2, 20.3)
extrude "Extrude49" add sketch "Sketch49" along normal blind 3
work_plane "WorkPlane50" AlongDistance -7.7 ExtraOffset 0
sketch "Sketch50" plane through (0, 0, -7.7) normal (0, 0, 1) x axis (1, 0, 0)
  line L1 (12.6, 15.9) -> (10.2, 15.9)
  line L2 (12.6, 20.3) -> (12.6, 15.9)
  line L3 (10.2, 20.3) -> (12.6, 20.3)
  line L4 (10.2, 15.9) -> (10.2, 20.3)
extrude "Extrude50" add sketch "Sketch50" along normal blind 1.21
fillet "Fillet4" radius 1.2
sketch "Sketch51" plane through (0, 0, 0) normal (1, 0, 0) x axis (0, 0, -1)
  circle C1 centre (6.2, -30.3) radius 0.55
extrude "Extrude51" cut sketch "Sketch51" distance 13.6
sketch "Sketch52" plane through (0, 0, 0) normal (1, 0, 0) x axis (0, 0, -1)
  circle C1 centre (6.2, 18.5) radius 0.55
extrude "Extrude52" cut sketch "Sketch52" distance 13.6
work_plane "WorkPlane1" AlongDistance -7.7 ExtraOffset 0
sketch "Sketch1" plane through (0, 0, -7.7) normal (0, 0, 1) x axis (1, 0, 0)
  line L1 (24.2, -27.5) -> (-24.2, -27.5)
  line L2 (24.2, 15.7) -> (24.2, -27.5)
  line L3 (-24.2, 15.7) -> (24.2, 15.7)
  line L4 (-24.2, -27.5) -> (-24.2, 15.7)
extrude "Extrude1" new body sketch "Sketch1" along normal blind 1.2
fillet "Fillet1" radius 5
fillet "Fillet2" radius 0.6
work_plane "WorkPlane2" AlongDistance -7.8 ExtraOffset 0
sketch "Sketch2" plane through (0, 0, -7.8) normal (0, 0, 1) x axis (1, 0, 0)
  circle C1 centre (-20.1, -23.4) radius 1.1
extrude "Extrude2" cut sketch "Sketch2" along normal blind 1.4
work_plane "WorkPlane3" AlongDistance -7.8 ExtraOffset 0
sketch "Sketch3" plane through (0, 0, -7.8) normal (0, 0, 1) x axis (1, 0, 0)
  circle C1 centre (-20.1, -23.4) radius 1.95
extrude "Extrude3" cut sketch "Sketch3" along normal blind 0.8
work_plane "WorkPlane4" AlongDistance -7.8 ExtraOffset 0
sketch "Sketch4" plane through (0, 0, -7.8) normal (0, 0, 1) x axis (1, 0, 0)
  circle C1 centre (-1.7, -23.5) radius 1.1
extrude "Extrude4" cut sketch "Sketch4" along normal blind 1.4
work_plane "WorkPlane5" AlongDistance -7.8 ExtraOffset 0
sketch "Sketch5" plane through (0, 0, -7.8) normal (0, 0, 1) x axis (1, 0, 0)
  circle C1 centre (-1.7, -23.5) radius 1.95
extrude "Extrude5" cut sketch "Sketch5" along normal blind 0.8
work_plane "WorkPlane6" AlongDistance -6.51 ExtraOffset 0
sketch "Sketch6" plane through (0, 0, -6.51) normal (0, 0, 1) x axis (1, 0, 0)
  line L1 (21.95, -0.5) -> (20.95, -0.5)
  line L2 (21.95, 4) -> (21.95, -0.5)
  line L3 (20.95, 4) -> (21.95, 4)
  line L4 (20.95, -0.5) -> (20.95, 4)
extrude "Extrude6" add sketch "Sketch6" along normal blind 1.01
work_plane "WorkPlane7" AlongDistance -6.51 ExtraOffset 0
sketch "Sketch7" plane through (0, 0, -6.51) normal (0, 0, 1) x axis (1, 0, 0)
  line L1 (19, 12.6) -> (11, 12.6)
  line L2 (19, 13.55) -> (19, 12.6)
  line L3 (11, 13.55) -> (19, 13.55)
  line L4 (11, 12.6) -> (11, 13.55)
extrude "Extrude7" add sketch "Sketch7" along normal blind 1.61
work_plane "WorkPlane8" AlongDistance -5.8 ExtraOffset 0
sketch "Sketch8" plane through (0, 0, -5.8) normal (0, 0, 1) x axis (1, 0, 0)
  line L1 (19, 13.5) -> (11, 13.5)
  line L2 (19, 14.35) -> (19, 13.5)
  line L3 (11, 14.35) -> (19, 14.35)
  line L4 (11, 13.5) -> (11, 14.35)
extrude "Extrude8" add sketch "Sketch8" along normal blind 0.75
work_plane "WorkPlane9" AlongDistance -6.8 ExtraOffset 0
sketch "Sketch9" plane through (0, 0, -6.8) normal (0, 0, 1) x axis (1, 0, 0)
  circle C1 centre (11, -15.3) radius 10.3
extrude "Extrude9" cut sketch "Sketch9" along normal blind 0.31
work_plane "WorkPlane10" AlongDistance -7.7 ExtraOffset 0
sketch "Sketch10" plane through (0, 0, -7.7) normal (0, 0, 1) x axis (1, 0, 0)
  line L1 (-11.95, -9.65) -> (-15.05, -9.65)
  line L2 (-9.75, -4.35) -> (-9.75, -7.45)
  line L3 (-15.05, -2.15) -> (-11.95, -2.15)
  line L4 (-17.25, -7.45) -> (-17.25, -4.35)
  line L5 (-11.95, -9.05) -> (-15.05, -9.05)
  line L6 (-10.35, -4.35) -> (-10.35, -7.45)
  line L7 (-15.05, -2.75) -> (-11.95, -2.75)
  line L8 (-16.65, -7.45) -> (-16.65, -4.35)
  arc A1 centre (-11.95, -7.45) radius 2.2 clockwise from (-9.75, -7.45) to (-11.95, -9.65)
  arc A2 centre (-11.95, -4.35) radius 2.2 clockwise from (-11.95, -2.15) to (-9.75, -4.35)
  arc A3 centre (-15.05, -4.35) radius 2.2 clockwise from (-17.25, -4.35) to (-15.05, -2.15)
  arc A4 centre (-15.05, -7.45) radius 2.2 clockwise from (-15.05, -9.65) to (-17.25, -7.45)
  arc A5 centre (-11.95, -7.45) radius 1.6 clockwise from (-10.35, -7.45) to (-11.95, -9.05)
  arc A6 centre (-11.95, -4.35) radius 1.6 clockwise from (-11.95, -2.75) to (-10.35, -4.35)
  arc A7 centre (-15.05, -4.35) radius 1.6 clockwise from (-16.65, -4.35) to (-15.05, -2.75)
  arc A8 centre (-15.05, -7.45) radius 1.6 clockwise from (-15.05, -9.05) to (-16.65, -7.45)
extrude "Extrude10" cut sketch "Sketch10" along normal blind 0.3
work_plane "WorkPlane11" AlongDistance -7.7 ExtraOffset 0
sketch "Sketch11" plane through (0, 0, -7.7) normal (0, 0, 1) x axis (1, 0, 0)
  line L1 (-2.95, -9.65) -> (-6.05, -9.65)
  line L2 (-0.75, -4.35) -> (-0.75, -7.45)
  line L3 (-6.05, -2.15) -> (-2.95, -2.15)
  line L4 (-8.25, -7.45) -> (-8.25, -4.35)
  line L5 (-2.95, -9.05) -> (-6.05, -9.05)
  line L6 (-1.35, -4.35) -> (-1.35, -7.45)
  line L7 (-6.05, -2.75) -> (-2.95, -2.75)
  line L8 (-7.65, -7.45) -> (-7.65, -4.35)
  arc A1 centre (-2.95, -7.45) radius 2.2 clockwise from (-0.75, -7.45) to (-2.95, -9.65)
  arc A2 centre (-2.95, -4.35) radius 2.2 clockwise from (-2.95, -2.15) to (-0.75, -4.35)
  arc A3 centre (-6.05, -4.35) radius 2.2 clockwise from (-8.25, -4.35) to (-6.05, -2.15)
  arc A4 centre (-6.05, -7.45) radius 2.2 clockwise from (-6.05, -9.65) to (-8.25, -7.45)
  arc A5 centre (-2.95, -7.45) radius 1.6 clockwise from (-1.35, -7.45) to (-2.95, -9.05)
  arc A6 centre (-2.95, -4.35) radius 1.6 clockwise from (-2.95, -2.75) to (-1.35, -4.35)
  arc A7 centre (-6.05, -4.35) radius 1.6 clockwise from (-7.65, -4.35) to (-6.05, -2.75)
  arc A8 centre (-6.05, -7.45) radius 1.6 clockwise from (-6.05, -9.05) to (-7.65, -7.45)
extrude "Extrude11" cut sketch "Sketch11" along normal blind 0.3
work_plane "WorkPlane12" AlongDistance -7.7 ExtraOffset 0
sketch "Sketch12" plane through (0, 0, -7.7) normal (0, 0, 1) x axis (1, 0, 0)
  line L1 (-5.7, -7.9) -> (-6.5, -7.9)
  line L2 (-5.7, -7.1) -> (-5.7, -7.9)
  line L3 (-6.5, -7.1) -> (-5.7, -7.1)
  line L4 (-6.5, -7.9) -> (-6.5, -7.1)
  line L5 (-4.1, -7.9) -> (-4.9, -7.9)
  line L6 (-4.1, -7.1) -> (-4.1, -7.9)
  line L7 (-4.9, -7.1) -> (-4.1, -7.1)
  line L8 (-4.9, -7.9) -> (-4.9, -7.1)
  line L9 (-2.5, -7.9) -> (-3.3, -7.9)
  line L10 (-2.5, -7.1) -> (-2.5, -7.9)
  line L11 (-3.3, -7.1) -> (-2.5, -7.1)
  line L12 (-3.3, -7.9) -> (-3.3, -7.1)
  line L13 (-5.7, -6.3) -> (-6.5, -6.3)
  line L14 (-5.7, -5.5) -> (-5.7, -6.3)
  line L15 (-6.5, -5.5) -> (-5.7, -5.5)
  line L16 (-6.5, -6.3) -> (-6.5, -5.5)
  line L17 (-4.1, -6.3) -> (-4.9, -6.3)
  line L18 (-4.1, -5.5) -> (-4.1, -6.3)
  line L19 (-4.9, -5.5) -> (-4.1, -5.5)
  line L20 (-4.9, -6.3) -> (-4.9, -5.5)
  line L21 (-2.5, -6.3) -> (-3.3, -6.3)
  line L22 (-2.5, -5.5) -> (-2.5, -6.3)
  line L23 (-3.3, -5.5) -> (-2.5, -5.5)
  line L24 (-3.3, -6.3) -> (-3.3, -5.5)
  line L25 (-5.7, -4.7) -> (-6.5, -4.7)
  line L26 (-5.7, -3.9) -> (-5.7, -4.7)
  line L27 (-6.5, -3.9) -> (-5.7, -3.9)
  line L28 (-6.5, -4.7) -> (-6.5, -3.9)
  line L29 (-4.1, -4.7) -> (-4.9, -4.7)
  line L30 (-4.1, -3.9) -> (-4.1, -4.7)
  line L31 (-4.9, -3.9) -> (-4.1, -3.9)
  line L32 (-4.9, -4.7) -> (-4.9, -3.9)
  line L33 (-2.5, -4.7) -> (-3.3, -4.7)
  line L34 (-2.5, -3.9) -> (-2.5, -4.7)
  line L35 (-3.3, -3.9) -> (-2.5, -3.9)
  line L36 (-3.3, -4.7) -> (-3.3, -3.9)
extrude "Extrude12" cut sketch "Sketch12" along normal blind 0.3
work_plane "WorkPlane13" AlongDistance -7.7 ExtraOffset 0
sketch "Sketch13" plane through (0, 0, -7.7) normal (0, 0, 1) x axis (1, 0, 0)
  line L1 (6.05, -9.65) -> (2.95, -9.65)
  line L2 (8.25, -4.35) -> (8.25, -7.45)
  line L3 (2.95, -2.15) -> (6.05, -2.15)
  line L4 (0.75, -7.45) -> (0.75, -4.35)
  line L5 (6.05, -9.05) -> (2.95, -9.05)
  line L6 (7.65, -4.35) -> (7.65, -7.45)
  line L7 (2.95, -2.75) -> (6.05, -2.75)
  line L8 (1.35, -7.45) -> (1.35, -4.35)
  arc A1 centre (6.05, -7.45) radius 2.2 clockwise from (8.25, -7.45) to (6.05, -9.65)
  arc A2 centre (6.05, -4.35) radius 2.2 clockwise from (6.05, -2.15) to (8.25, -4.35)
  arc A3 centre (2.95, -4.35) radius 2.2 clockwise from (0.75, -4.35) to (2.95, -2.15)
  arc A4 centre (2.95, -7.45) radius 2.2 clockwise from (2.95, -9.65) to (0.75, -7.45)
  arc A5 centre (6.05, -7.45) radius 1.6 clockwise from (7.65, -7.45) to (6.05, -9.05)
  arc A6 centre (6.05, -4.35) radius 1.6 clockwise from (6.05, -2.75) to (7.65, -4.35)
  arc A7 centre (2.95, -4.35) radius 1.6 clockwise from (1.35, -4.35) to (2.95, -2.75)
  arc A8 centre (2.95, -7.45) radius 1.6 clockwise from (2.95, -9.05) to (1.35, -7.45)
extrude "Extrude13" cut sketch "Sketch13" along normal blind 0.3
work_plane "WorkPlane14" AlongDistance -7.7 ExtraOffset 0
sketch "Sketch14" plane through (0, 0, -7.7) normal (0, 0, 1) x axis (1, 0, 0)
  line L1 (4.375, -8.325) -> (3.775, -8.325)
  line L2 (4.375, -7.725) -> (4.375, -8.325)
  line L3 (3.775, -7.725) -> (4.375, -7.725)
  line L4 (3.775, -8.325) -> (3.775, -7.725)
  line L5 (6.075, -8.325) -> (5.475, -8.325)
  line L6 (6.075, -7.725) -> (6.075, -8.325)
  line L7 (5.475, -7.725) -> (6.075, -7.725)
  line L8 (5.475, -8.325) -> (5.475, -7.725)
  line L9 (3.525, -7.475) -> (2.925, -7.475)
  line L10 (3.525, -6.875) -> (3.525, -7.475)
  line L11 (2.925, -6.875) -> (3.525, -6.875)
  line L12 (2.925, -7.475) -> (2.925, -6.875)
  line L13 (5.225, -7.475) -> (4.625, -7.475)
  line L14 (5.225, -6.875) -> (5.225, -7.475)
  line L15 (4.625, -6.875) -> (5.225, -6.875)
  line L16 (4.625, -7.475) -> (4.625, -6.875)
  line L17 (6.925, -7.475) -> (6.325, -7.475)
  line L18 (6.925, -6.875) -> (6.925, -7.475)
  line L19 (6.325, -6.875) -> (6.925, -6.875)
  line L20 (6.325, -7.475) -> (6.325, -6.875)
  line L21 (2.675, -6.625) -> (2.075, -6.625)
  line L22 (2.675, -6.025) -> (2.675, -6.625)
  line L23 (2.075, -6.025) -> (2.675, -6.025)
  line L24 (2.075, -6.625) -> (2.075, -6.025)
  line L25 (4.375, -6.625) -> (3.775, -6.625)
  line L26 (4.375, -6.025) -> (4.375, -6.625)
  line L27 (3.775, -6.025) -> (4.375, -6.025)
  line L28 (3.775, -6.625) -> (3.775, -6.025)
  line L29 (6.075, -6.625) -> (5.475, -6.625)
  line L30 (6.075, -6.025) -> (6.075, -6.625)
  line L31 (5.475, -6.025) -> (6.075, -6.025)
  line L32 (5.475, -6.625) -> (5.475, -6.025)
  line L33 (3.525, -5.775) -> (2.925, -5.775)
  line L34 (3.525, -5.175) -> (3.525, -5.775)
  line L35 (2.925, -5.175) -> (3.525, -5.175)
  line L36 (2.925, -5.775) -> (2.925, -5.175)
  line L37 (5.225, -5.775) -> (4.625, -5.775)
  line L38 (5.225, -5.175) -> (5.225, -5.775)
  line L39 (4.625, -5.175) -> (5.225, -5.175)
  line L40 (4.625, -5.775) -> (4.625, -5.175)
  line L41 (6.925, -5.775) -> (6.325, -5.775)
  line L42 (6.925, -5.175) -> (6.925, -5.775)
  line L43 (6.325, -5.175) -> (6.925, -5.175)
  line L44 (6.325, -5.775) -> (6.325, -5.175)
  line L45 (2.675, -4.925) -> (2.075, -4.925)
  line L46 (2.675, -4.325) -> (2.675, -4.925)
  line L47 (2.075, -4.325) -> (2.675, -4.325)
  line L48 (2.075, -4.925) -> (2.075, -4.325)
  line L49 (4.375, -4.925) -> (3.775, -4.925)
  line L50 (4.375, -4.325) -> (4.375, -4.925)
  line L51 (3.775, -4.325) -> (4.375, -4.325)
  line L52 (3.775, -4.925) -> (3.775, -4.325)
  line L53 (6.075, -4.925) -> (5.475, -4.925)
  line L54 (6.075, -4.325) -> (6.075, -4.925)
  line L55 (5.475, -4.325) -> (6.075, -4.325)
  line L56 (5.475, -4.925) -> (5.475, -4.325)
  line L57 (3.525, -4.075) -> (2.925, -4.075)
  line L58 (3.525, -3.475) -> (3.525, -4.075)
  line L59 (2.925, -3.475) -> (3.525, -3.475)
  line L60 (2.925, -4.075) -> (2.925, -3.475)
  line L61 (5.225, -4.075) -> (4.625, -4.075)
  line L62 (5.225, -3.475) -> (5.225, -4.075)
  line L63 (4.625, -3.475) -> (5.225, -3.475)
  line L64 (4.625, -4.075) -> (4.625, -3.475)
extrude "Extrude14" cut sketch "Sketch14" along normal blind 0.3
work_plane "WorkPlane15" AlongDistance -7.7 ExtraOffset 0
sketch "Sketch15" plane through (0, 0, -7.7) normal (0, 0, 1) x axis (1, 0, 0)
  line L1 (15.05, -9.65) -> (11.95, -9.65)
  line L2 (17.25, -4.35) -> (17.25, -7.45)
  line L3 (11.95, -2.15) -> (15.05, -2.15)
  line L4 (9.75, -7.45) -> (9.75, -4.35)
  arc A1 centre (15.05, -7.45) radius 2.2 clockwise from (17.25, -7.45) to (15.05, -9.65)
  arc A2 centre (15.05, -4.35) radius 2.2 clockwise from (15.05, -2.15) to (17.25, -4.35)
  arc A3 centre (11.95, -4.35) radius 2.2 clockwise from (9.75, -4.35) to (11.95, -2.15)
  arc A4 centre (11.95, -7.45) radius 2.2 clockwise from (11.95, -9.65) to (9.75, -7.45)
extrude "Extrude15" cut sketch "Sketch15" along normal blind 0.3
work_plane "WorkPlane1" AlongDistance -5.8 ExtraOffset 0
sketch "Sketch1" plane through (0, 0, -5.8) normal (0, 0, 1) x axis (1, 0, 0)
  line L1 (8.4, -6.9) -> (-21.6, -6.9)
  line L2 (8.4, 13.1) -> (8.4, -6.9)
  line L3 (-21.6, 13.1) -> (8.4, 13.1)
  line L4 (-21.6, -6.9) -> (-21.6, 13.1)
extrude "Extrude1" new body sketch "Sketch1" along normal blind 5 bodies "LiPo 30x20x5"
work_plane "WorkPlane2" AlongDistance -6.5 ExtraOffset 0
sketch "Sketch2" plane through (0, 0, -6.5) normal (0, 0, 1) x axis (1, 0, 0)
  circle C1 centre (15.5, 4) radius 5
extrude "Extrude2" new body sketch "Sketch2" along normal blind 2.7 bodies "Vibration motor 10x2.7"
work_plane "WorkPlane3" AlongDistance -1.3 ExtraOffset 0
sketch "Sketch3" plane through (0, 0, -1.3) normal (0, 0, 1) x axis (1, 0, 0)
  line L1 (21.6, -24.9) -> (0.6, -24.9)
  line L2 (21.6, -7.1) -> (21.6, -24.9)
  line L3 (0.6, -7.1) -> (21.6, -7.1)
  line L4 (0.6, -24.9) -> (0.6, -7.1)
extrude "Extrude3" new body sketch "Sketch3" along normal blind 1 bodies "XIAO ESP32-S3 (upside down)"
work_plane "WorkPlane4" AlongDistance -4.5 ExtraOffset 0
sketch "Sketch4" plane through (0, 0, -4.5) normal (0, 0, 1) x axis (1, 0, 0)
  line L1 (22, -20.45) -> (14.6, -20.45)
  line L2 (22, -11.55) -> (22, -20.45)
  line L3 (14.6, -11.55) -> (22, -11.55)
  line L4 (14.6, -20.45) -> (14.6, -11.55)
extrude "Extrude4" add sketch "Sketch4" along normal blind 3.2
work_plane "WorkPlane5" AlongDistance -3.8 ExtraOffset 0
sketch "Sketch5" plane through (0, 0, -3.8) normal (0, 0, 1) x axis (1, 0, 0)
  line L1 (14.6, -23.9) -> (1.6, -23.9)
  line L2 (14.6, -8.1) -> (14.6, -23.9)
  line L3 (1.6, -8.1) -> (14.6, -8.1)
  line L4 (1.6, -23.9) -> (1.6, -8.1)
extrude "Extrude5" add sketch "Sketch5" along normal blind 2.5
work_plane "WorkPlane6" AlongDistance -6.5 ExtraOffset 0
sketch "Sketch6" plane through (0, 0, -6.5) normal (0, 0, 1) x axis (1, 0, 0)
  line L1 (-4, -24.9) -> (-18, -24.9)
  line L2 (-4, -10.9) -> (-4, -24.9)
  line L3 (-18, -10.9) -> (-4, -10.9)
  line L4 (-18, -24.9) -> (-18, -10.9)
extrude "Extrude6" new body sketch "Sketch6" along normal blind 6.2 bodies "DS3231 14x14 (no header)"
work_plane "WorkPlane7" AlongDistance -6.8 ExtraOffset 0
sketch "Sketch7" plane through (0, 0, -6.8) normal (0, 0, 1) x axis (1, 0, 0)
  circle C1 centre (11, -15.3) radius 10
extrude "Extrude7" new body sketch "Sketch7" along normal blind 0.5 bodies "Piezo disc 20mm"
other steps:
create_component "CreateComponent1"
create_component "CreateComponent53"
create_component "CreateComponent54"
create_component "CreateComponent55"
named bodies: "Shell", "Back", "LiPo 30x20x5", "Vibration motor 10x2.7", "XIAO ESP32-S3 (upside down)", "DS3231 14x14 (no header)", "Piezo disc 20mm"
